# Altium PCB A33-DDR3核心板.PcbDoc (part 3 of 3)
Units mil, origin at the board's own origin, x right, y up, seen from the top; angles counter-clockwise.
Board outline 2370 x 2515 mil, 4 copper layers (TOP, GND02, PWR03, BOTTOM), stack 38.4 mil thick; 39 components, 64 nets, 546 pads, 403 vias.
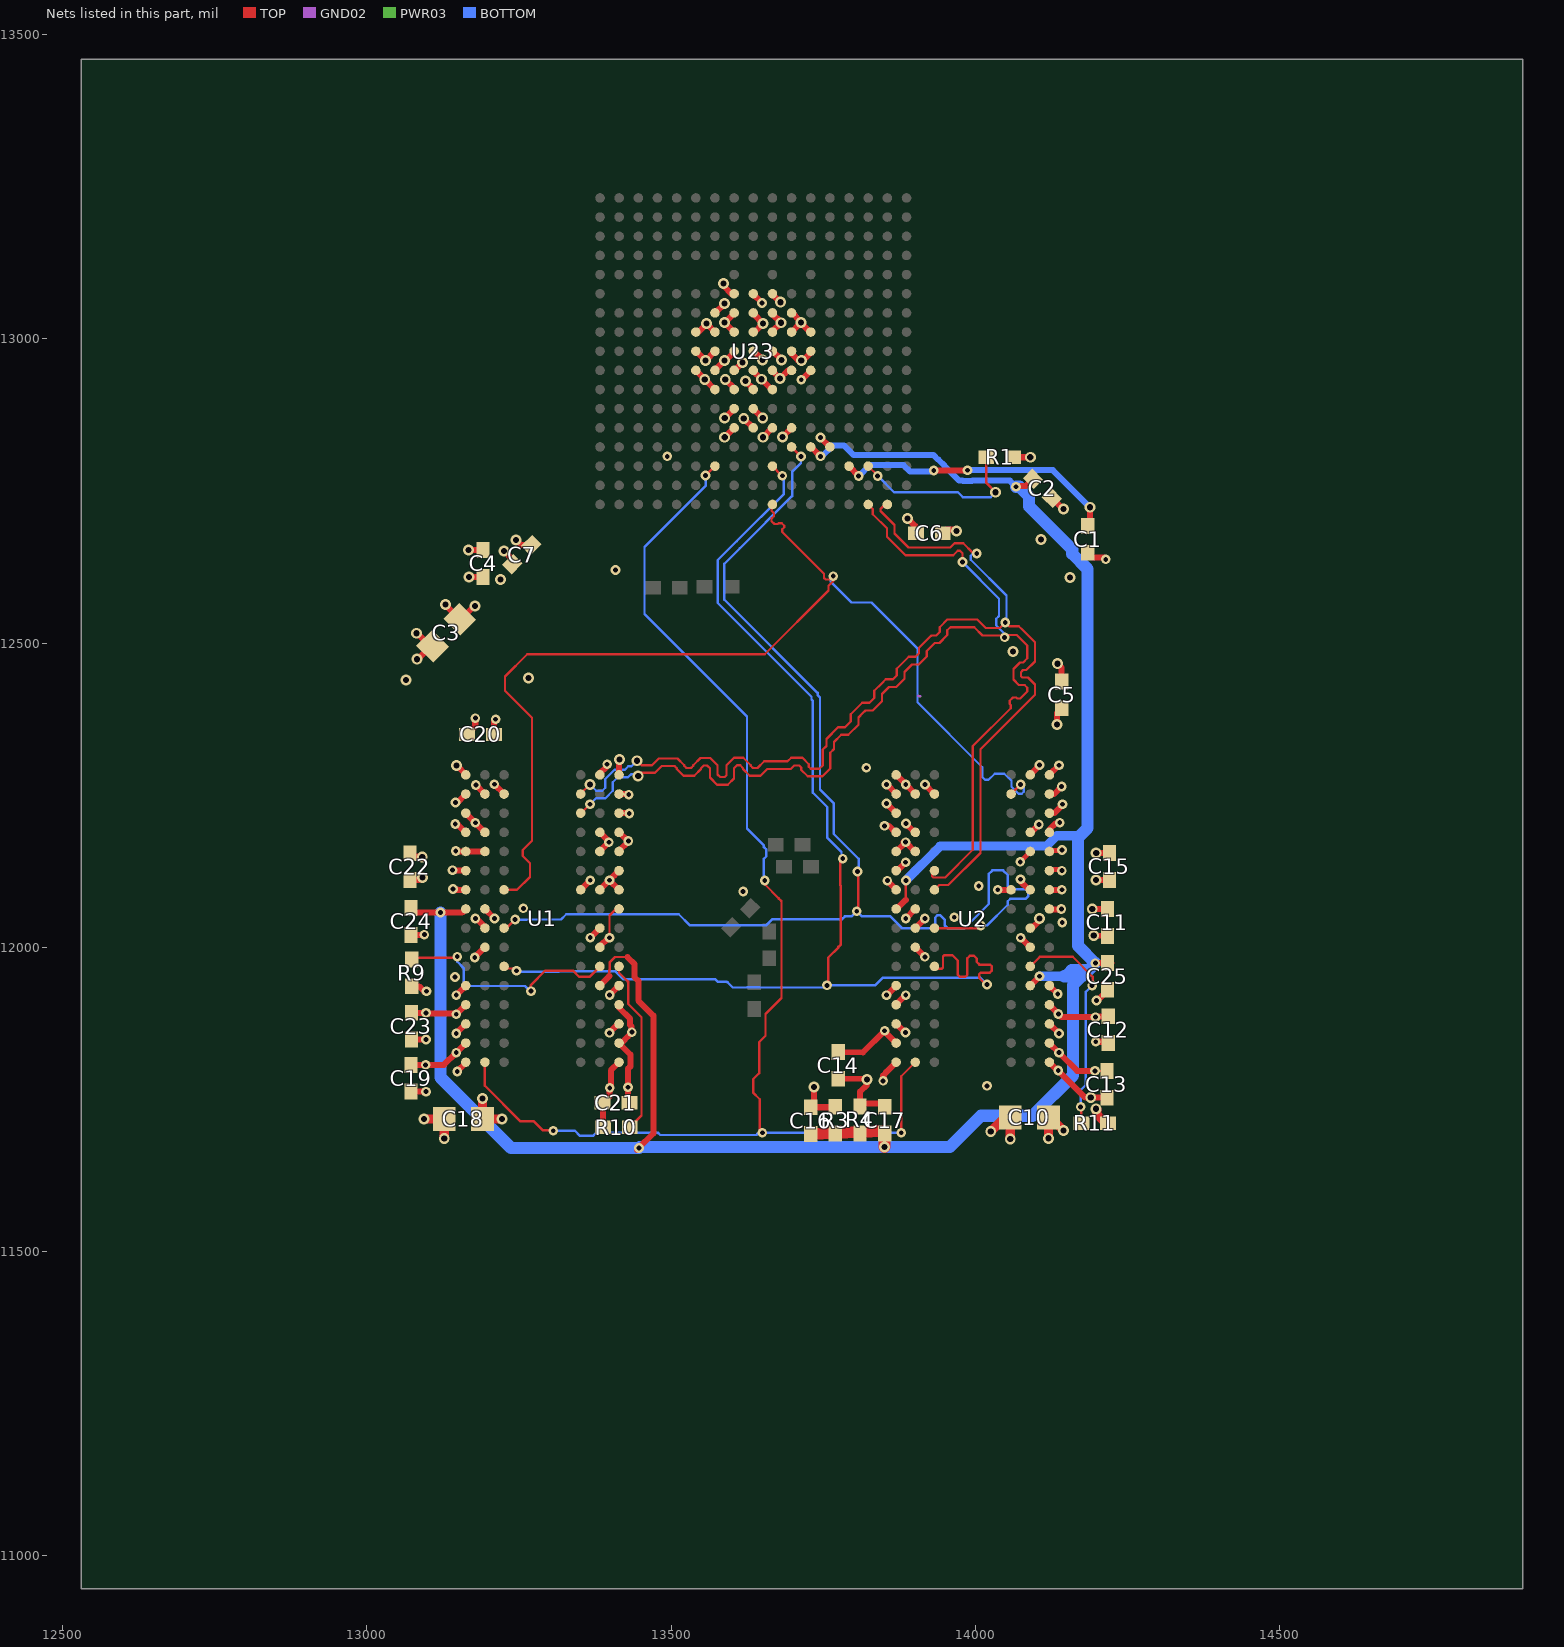
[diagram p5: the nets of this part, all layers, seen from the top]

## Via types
v1: diameter 16, hole 8, TOP to BOTTOM, 320 vias
v2: diameter 18, hole 10, TOP to BOTTOM, 83 vias

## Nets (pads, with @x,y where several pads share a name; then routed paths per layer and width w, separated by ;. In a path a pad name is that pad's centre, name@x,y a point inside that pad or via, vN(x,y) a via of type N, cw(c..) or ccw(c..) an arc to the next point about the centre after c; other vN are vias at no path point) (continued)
DQS0N: U1.G3 U2.B7 U23.K1 | length 1804.6
  TOP w3.7: U1.G3@13225.37,12094.33 13246.7,12094.33 13267.86,12115.48 13267.86,12138 13255.93,12149.93 13255.93,12159.62 13271.34,12175.04 13271.34,12377.18 13226.81,12421.71 13226.81,12444.98 13263.25,12481.43 13653.82,12481.43 13758.75,12586.36 13758.75,12594.3 13766.62,12602.17 v1(13766.62,12609.97) 13761.01,12604.37 13753.99,12604.37 13751.48,12606.88 13751.48,12613.98 13682.79,12682.67 13682.79,12686.92 13686.02,12690.15 13686.02,12692.97 13682,12696.99 13676.77,12696.99 13675.48,12695.71 13669.76,12695.71 13665.14,12700.32 13665.14,12704.63 13668.93,12708.41 13668.93,12713.9 13665.14,12717.68 13665.14,12720.92 13666.56,12722.33 U23.K1@13666.56,12727.82
  TOP w4: U2.B7@14058.91,12251.81 v1(14074.66,12267.55)
  BOTTOM w3.7: v1(13766.62,12609.97) 13762.01,12605.36 13762.01,12601.32 13796.73,12566.59 13829.3,12566.59 13905.01,12490.88 13905.01,12402.58 14011.71,12295.88 14011.71,12279.65 14016.16,12275.2 14021.95,12275.2 14032.01,12285.26 14047.6,12285.26 14059.46,12273.4 14059.46,12263.75 14071.04,12252.16 14076.5,12252.16 14079.89,12255.56 14079.89,12262.32 v1(14074.66,12267.55)
DQS1: U1.C7 U2.F3 U23.R1 | length 1918.8
  TOP w3.7: U1.C7@13351.35,12220.31 13351.83,12220.31 v1(13366.49,12234.98) ; v2(13445.89,12281.28) 13451.26,12286.66 13473.6,12286.66 13484.68,12297.74 13505.45,12297.74 13509.15,12294.04 13509.15,12293.05 13520.17,12282.03 13537.92,12282.03 13548.95,12293.05 13548.95,12294.04 13553.52,12298.61 13559.17,12298.61 13563.75,12294.04 13563.75,12285.95 13563.75,12278.89 13575.46,12267.18 13593.23,12267.18 13603.55,12277.5 13603.55,12294.04 13608.44,12298.93 13613.45,12298.93 13618.35,12294.04 13618.35,12293.05 13629.37,12282.03 13647.12,12282.03 13658.15,12293.05 13696.68,12293.05 13702.5,12298.86 13710.64,12298.86 13713.96,12295.54 13713.96,12291.37 13724.47,12280.86 13748.9,12280.86 13761.71,12293.67 13761.71,12319.62 13767.76,12325.67 13767.76,12337.2 13779.67,12349.11 13791.2,12349.11 13807.89,12365.81 13807.89,12377.71 13814.67,12384.48 13819.43,12389.24 13831.33,12389.24 13846.5,12404.41 13846.5,12416.32 13858.04,12427.85 13869.94,12427.85 13883.5,12441.41 13883.5,12452.46 13895.9,12464.85 13896.53,12464.85 13906.94,12464.85 13920.13,12478.04 13920.13,12486.95 13933.25,12500.07 13941.05,12500.07 13954.07,12513.09 13954.07,12520.89 13959.26,12526.08 13998.22,12526.08 14011.89,12512.41 14045.23,12512.41 v1(14048.31,12509.33) ; U23.R1@13824.04,12727.82 13831.65,12720.21 13831.65,12711.93 13854.82,12688.76 13854.82,12674.74 13885.19,12644.38 13963.97,12644.38 13971.2,12651.6 13975.07,12651.6 13978.89,12647.78 v1(13978.89,12633.06) ; U2.F3@13932.93,12125.83 13928.74,12121.64 13928.74,12117 13931.04,12114.7 13950.55,12114.7 13995.99,12160.14 13995.99,12330.56 14058.37,12392.94 14058.37,12398.18 14056.71,12399.84 14056.71,12405.07 14061.94,12410.31 14067.17,12410.31 14068.84,12408.64 14074.07,12408.64 14085.63,12420.2 14085.63,12426.63 14081.44,12430.82 14071.92,12430.82 14062.7,12440.04 14062.7,12457.28 14073.47,12468.05 14078.7,12468.05 14085.63,12474.98 14085.63,12496.02 14068.38,12513.26 14052.24,12513.26 v1(14048.31,12509.33) ; v1@14048.31,12508.28 v1(14048.31,12509.33)
  BOTTOM w3.7: v1(13366.49,12234.98) 13376.34,12244.83 13391.99,12244.83 13404.2,12257.03 13404.2,12271.17 13412.26,12279.24 13429.16,12279.24 13434.69,12284.77 13442.4,12284.77 v2(13445.89,12281.28) ; v1(13978.89,12633.06) 14039.06,12572.89 14039.06,12544.54 14034.55,12540.03 14034.55,12528.8 14048.31,12515.04 v1(14048.31,12509.33)
DQS1N: U1.B7 U2.G3 U23.T1 | length 1931.6
  TOP w3.7: U1.B7@13351.35,12251.81 13351.35,12252.48 13366.03,12267.16 13366.36,12267.16 v2(13366.65,12267.45) ; v2@13444.09,12306.48 13451.41,12299.16 13468.42,12299.16 13479.5,12310.24 13510.62,12310.24 13521.65,12299.22 13521.65,12298.23 13525.35,12294.53 13532.75,12294.53 13536.45,12298.23 13536.45,12299.22 13548.34,12311.11 13564.35,12311.11 13576.25,12299.21 13576.25,12284.07 13580.64,12279.68 13588.05,12279.68 13591.05,12282.67 13591.05,12299.22 13603.26,12311.43 13618.63,12311.43 13630.85,12299.22 13630.85,12298.23 13634.55,12294.53 13641.95,12294.53 13652.97,12305.55 13691.51,12305.55 13697.32,12311.36 13715.82,12311.36 13726.46,12300.72 13726.46,12296.55 13729.65,12293.36 13743.72,12293.36 13749.21,12298.84 13749.21,12324.8 13755.26,12330.85 13755.26,12336.08 13755.26,12342.38 13774.5,12361.61 13786.02,12361.61 13795.39,12370.98 13795.39,12382.89 13814.25,12401.74 13826.15,12401.74 13834,12409.59 13834,12421.49 13846.97,12434.46 13852.86,12440.35 13864.76,12440.35 13871,12446.59 13871,12457.63 13890.72,12477.35 13896.53,12477.35 13901.76,12477.35 13907.63,12483.22 13907.63,12492.13 13924.04,12508.54 13928.07,12512.57 13935.88,12512.57 13941.57,12518.26 13941.57,12526.07 13954.08,12538.58 14003.4,12538.58 14017.07,12524.91 14040.43,12524.91 v1(14049.4,12533.88) 14055.62,12527.65 14071.67,12527.65 14077.22,12522.1 14098.13,12501.19 14098.13,12469.8 14083.87,12455.55 14078.65,12455.55 14075.2,12452.1 14075.2,12445.22 14077.1,12443.32 14086.61,12443.32 14098.13,12431.81 14098.13,12415.02 14008.49,12325.38 14008.49,12154.96 13955.73,12102.2 13940.8,12102.2 U2.G3@13932.93,12094.33 ; U23.T1@13855.53,12727.82 13851.76,12727.82 13844.15,12720.21 13844.15,12717.11 13867.32,12693.94 13867.32,12679.92 13890.36,12656.88 13958.8,12656.88 13966.02,12664.1 13980.25,12664.1 13995.64,12648.71 14000.94,12648.71 v1(14002.55,12647.11)
  BOTTOM w3.7: v2(13366.65,12267.45) 13376.77,12257.33 13386.81,12257.33 13391.7,12262.21 13391.7,12276.35 13407.09,12291.74 13423.98,12291.74 13429.52,12297.27 13434.84,12297.27 v2(13444.04,12306.48) ; v1(14002.55,12647.11) 13996.25,12647.11 13992.74,12643.59 13992.74,12636.89 14051.56,12578.07 14051.56,12539.36 14049.4,12537.2 v1(14049.4,12533.88)
DRAS: U1.J3 U2.J3 U23.L4 | length 2126.7
  TOP w4: U1.J3@13225.37,12031.34 13229.53,12031.34 v1(13243.53,12045.34) ; U23.L4@13698.05,12822.31 v1(13713.52,12806.84) ; v1(13805.08,12059.16) 13805.08,12062.51 13807.84,12065.27 13807.84,12123.1 v1(13806.47,12124.47) ; U2.J3@13932.93,12031.34 14004.87,12031.35 v1(14009.18,12035.65)
  BOTTOM w4: v1(13243.53,12045.34) 13262.97,12045.34 13263.1,12045.47 13318.79,12045.47 13327.53,12054.21 13512.48,12054.21 13530.43,12036.26 13656.65,12036.26 13666.53,12046.14 13781.2,12046.14 13785.56,12050.5 13796.41,12050.5 v1(13805.08,12059.16) 13813.15,12051.09 13859.74,12051.09 13879.48,12031.35 13930.17,12031.35 13934.17,12035.35 13934.17,12048.67 13938.17,12052.67 13941.88,12052.67 13950.17,12044.38 13950.17,12035.35 13954.17,12031.35 13982.71,12031.35 14022.29,12070.93 14022.29,12120.42 14028.08,12126.22 14045.89,12126.22 14053.51,12118.59 14053.51,12099.44 14057.51,12095.44 14082.89,12095.44 14086.89,12091.44 14086.89,12083.44 14082.89,12079.44 14057.51,12079.44 14053.51,12075.44 14053.51,12069.76 14019.41,12035.65 v1(14009.18,12035.65) ; v1(13713.52,12806.84) 13713.52,12796.19 13700.23,12782.9 13700.23,12782.73 13699.06,12781.55 13699.06,12777.32 13698.83,12777.09 13698.83,12741.62 13697.36,12740.16 13697.36,12740.11 13612.92,12655.66 13612.87,12655.66 13587.63,12630.43 13587.63,12571.22 13740.79,12418.06 13740.79,12414.64 13744.79,12410.64 13744.79,12259.08 13767.01,12236.86 13767.01,12186.52 13808.44,12145.09 13808.44,12127.53 13807,12126.09 13807,12125 v1(13806.47,12124.47)
DRST: U1.T2 U2.T2 U23.G3 | length 2154.7
  TOP w4: U1.T2@13193.87,11810.86 13193.87,11772.13 13252.38,11713.62 13274.28,11713.62 13289.16,11698.74 13305.61,11698.74 v1(13306.24,11698.11) ; v1@13557.75,12775.34 v1(13556.6,12775.34) U23.G3@13572.07,12790.81 ; v1(13649.95,11694.8) 13645.61,11699.14 13645.61,11749.96 13634.76,11760.81 13634.76,11782.8 13644.84,11792.88 13644.84,11844.1 13655.19,11854.45 13655.19,11890.19 13681.49,11916.49 13681.49,12074.98 13680.77,12075.7 13680.77,12076.25 13676.77,12080.25 13676.77,12080.53 13654.77,12102.53 13654.77,12105.11 13653.82,12106.06 v1(13653.82,12109.68) ; v1(13878.28,11694.8) 13878.28,11787.72 U2.T2@13901.43,11810.87
  BOTTOM w4: v1(13306.24,11698.11) 13341.76,11698.11 13349.57,11690.3 13372.38,11690.3 13376.66,11694.58 13478.61,11694.58 13482.04,11691.15 13640.09,11691.15 13641.9,11692.96 13648.11,11692.96 v1(13649.95,11694.8) v1(13878.28,11694.8) ; v1(13556.6,12775.34) 13556.6,12758.45 13456.19,12658.04 13456.19,12547.64 13624.79,12379.03 13624.79,12194.88 13652.6,12167.08 13652.6,12164.55 13656.44,12160.71 13656.44,12149.11 13652.6,12145.27 13652.6,12110.91 v1(13653.82,12109.68)
DVREF: C2.2 C16.1 C17.2 C24.2 C25.2 R3.1 R4.2 U1.H1 U1.M8 U2.H1 U2.M8 U23.M4 | length 4210.7
  TOP w4: U1.M8@13382.85,11936.85 13382.85,11936.99 13398.28,11952.42 13398.28,11961.89 13398.87,11962.48 13398.87,11974.75 13407.94,11983.82 13428.18,11983.82 ; U23.M4@13729.55,12822.31 13744.59,12807.27 v1@13745.16,12807.27 ; R3.1@13769.95,11693.57 13810.14,11698.57 R4.2@13810.48,11693.91 13850.67,11698.91 C17.2@13851.01,11693.57 ; U2.H1@13869.94,12062.84 13884.77,12077.67 13886.03,12077.67 v1(13886.03,12109.67)
  TOP w10: C24.2@13072.35,12064.25 13079.44,12057.16 v1(13121.03,12057.16) 13121.46,12056.73 13156.27,12056.73 U1.H1@13162.38,12062.83 ; U1.M8@13382.85,11936.85 13398.28,11952.27 13398.28,11952.42 ; 13428.18,11983.82 13439.85,11972.15 13439.85,11950.88 13440.53,11950.2 13446.1,11944.62 13446.1,11912.17 13470.73,11887.53 13470.73,11693.69 v1(13447.03,11669.98) v1@13443.78,11666.74 ; U23.M4@13729.55,12822.31 13730.12,12822.31 13745.16,12807.27 v1(13745.49,12806.94) ; U2.H1@13869.94,12062.84 13871.2,12062.84 13886.03,12077.67 ; v1(14066.81,12756.87) 14068.34,12758.4 14083.56,12758.4 C2.2@14094.94,12769.78 ; U2.M8@14090.41,11936.85 v1(14105.72,11952.17) ; v1(14197.47,11973.71) 14223.9,11973.71 C25.2@14217.33,11973.85
  TOP w20: C16.1@13729.74,11692.88 13850.33,11697.88 C17.2@13851.01,11693.57 v2(13851.01,11671.57)
  BOTTOM w10: v1(13745.49,12806.94) 13748.05,12806.94 13765.67,12824.57 13784.54,12824.57 13800.23,12808.87 13931.51,12808.87 13938.63,12801.75 13939.15,12801.75 13949.69,12791.21 13949.69,12790.69 13973.46,12766.92 13979.19,12766.92 13979.85,12766.26 13994.68,12766.26 13995.34,12766.92 14056.76,12766.92 v1(14066.81,12756.87)
  BOTTOM w15: v1(13886.03,12109.67) 13942.47,12166.11 14116.84,12166.11 14133.89,12183.16 14172.04,12183.16 ; v1(14105.72,11952.17) 14146.42,11952.17 ; v1(14197.47,11973.71) v1@14197.47,11975.34
  BOTTOM w20: 13121.03,11882.57 13121.03,11785.61 13236.66,11669.98 v1(13447.03,11669.98) 13448.51,11671.46 v2@13851.12,11671.46 ; 13121.04,11882.58 13121.04,11901.56 v1(13121.03,12057.16) ; v2(13851.01,11671.57) v2@13851.12,11671.46 ; v1(14066.81,12756.87) 14072.63,12756.87 14088.59,12740.9 14088.59,12724.5 14159.5,12653.6 14159.5,12646.6 14184.55,12621.55 14184.55,12195.67 14172.04,12183.16 14168.88,12180 14168.88,12002.3 v1(14197.47,11973.71) 14186.01,11962.26 ; 14146.42,11952.17 14148.64,11952.17 14158.73,11962.26 14186.01,11962.26 ; v2@13851.12,11671.46 13957.99,11671.46 14009.29,11722.77 14094.21,11722.77 14160.64,11789.19 14160.64,11938.04 14184.36,11961.76 14185.52,11961.76 14186.01,11962.26
DWE: U1.L3 U2.L3 U23.K3 | length 2066.5
  TOP w4: v1(13245.76,11961.28) 13244.78,11962.25 13243.75,11962.25 13243.05,11962.95 13242.47,11962.95 13240.54,11964.89 13228.83,11964.89 U1.L3@13227.55,11966.17 ; U23.K3@13666.56,12790.81 13680.83,12776.54 13681.27,12776.54 v1(13682.81,12775) ; v1(13756.27,11937.19) 13758.22,11939.14 13758.22,11983.07 13774.87,11999.73 13774.87,12000.36 13779.2,12004.68 13779.2,12100.81 13777.93,12102.08 13777.93,12141.21 v1(13782.24,12145.52) ; U2.L3@13932.93,11968.35 13937.1,11964.18 13944.56,11964.18 13946.97,11966.58 13946.97,11984.56 13949.31,11986.89 13962.24,11986.89 13971.16,11977.97 13971.16,11954.94 13975.02,11951.08 13983.47,11951.08 13987.16,11954.77 13987.16,11981.82 13991.16,11985.82 13997.78,11985.82 14002.39,11981.21 14002.39,11975.86 14006.88,11971.38 14024.31,11971.38 14027.14,11968.55 14027.14,11961.45 14023.34,11957.66 14008.6,11957.66 14006.5,11955.55 14006.5,11949.52 14017.23,11938.8 v1@14019.22,11938.8 ; v1@14019.23,11938.79 v1(14019.3,11938.79) ; U1.L3@13227.55,11966.17 U1.L3@13225.37,11968.34 U1.L3@13227.55,11966.17
  BOTTOM w4: v1(13245.76,11961.28) 13246.74,11961.28 13248.59,11959.42 13258.02,11959.42 13258.2,11959.25 13314.58,11959.25 13316.07,11960.74 13407.73,11960.74 13421.52,11946.95 13573,11946.95 13576.5,11943.45 13591.2,11943.45 13592.6,11942.05 13593.02,11942.05 13601.37,11933.7 13624.56,11933.7 13624.98,11934.12 13644.87,11934.12 13645.29,11933.7 13752.78,11933.7 v1(13756.27,11937.19) 13835.24,11937.19 13848.11,11950.07 14008.02,11950.07 v1(14019.3,11938.79) ; v1(13682.81,12775) 13685.36,12772.45 13685.36,12745.08 13607.95,12667.66 13607.9,12667.66 13576.65,12636.42 13576.65,12625.11 13576.41,12624.88 13576.41,12566.16 13730.79,12411.78 13730.79,12407 13732.79,12405 13732.79,12254.11 13756.97,12229.93 13756.97,12179.59 13780.07,12156.48 13780.07,12147.69 v1(13782.24,12145.52)
DZQ: R1.2 U23.R3 | length 298.4
  TOP w3.7: U23.R3@13824.04,12790.81 13839.21,12775.64 13839.21,12775.07 v1(13839.58,12774.7)
  TOP w4: R1.2@14018.23,12805.45 14018.23,12763.23 v2(14033.58,12747.88)
  BOTTOM w4: v1(13839.58,12774.7) 13839.98,12774.7 13866.67,12748.01 13971.4,12748.01 13979.77,12739.64 14025.35,12739.64 v2(14033.58,12747.88)
GND: C1.1 C2.1 C3.1 C4.1 C5.1 C6.1 C7.1 C10.1 C11.1 C12.1 C13.2 C14.2 C15.2 C17.1 C18.1 C19.1 C20.1 C21.2 C22.2 C23.2 C24.1 C25.1 R1.1 R4.1 R9.1 R10.1 R11.1 U1.A9 U1.B1 U1.B3 U1.B9 U1.D1 U1.D8 U1.E1 U1.E2 U1.E8 U1.F9 U1.G1 U1.G8 U1.G9 U1.J2 U1.J8 U1.M1 U1.M9 U1.P1 U1.P9 U1.T1 U1.T9 U2.A9 U2.B1 U2.B3 U2.B9 U2.D1 U2.D8 U2.E1 U2.E2 U2.E8 U2.F9 U2.G1 U2.G8 U2.G9 U2.J2 U2.J8 U2.M1 U2.M9 U2.P1 U2.P9 U2.T1 U2.T9 U23.F8 U23.F9 U23.F10 U23.G7 U23.G8 U23.G9 U23.G10 U23.G11 U23.H7 U23.H8 U23.H9 U23.H10 U23.H11 U23.H12 U23.J7 U23.J8 U23.J9 U23.J10 U23.J11 U23.J12 U23.K7 U23.K8 U23.K9 U23.K10 U23.K11 U23.K12 U23.L8 U23.L9 U23.L10 U23.L11 U23.M8 U23.M9 U23.M10 U23.N4 | length 3159.8
  TOP w3.7: v1(13745.53,12837.94) 13745.53,12837.59 13760.81,12822.31 U23.N4@13761.04,12822.31
  TOP w4: v1(13146.63,11858.12) U1.P1@13162.38,11873.86 ; v1@13148.18,12094.33 U1.G1@13162.38,12094.33 ; v1(13178.13,12047.09) U1.J2@13193.87,12031.34 U1.J2@13193.87,12033.75 ; v1(13367.1,12015.6) U1.J8@13382.85,12031.34 ; U1.G8@13382.85,12094.33 v1(13398.59,12110.08) ; 13400.84,11797.36 U1.T9@13414.35,11810.86 ; U1.M9@13412.91,11935.42 U1.M9@13414.35,11936.85 ; U23.F9@13540.57,12979.79 U23.F9@13541.13,12979.79 ; U23.F10@13544.51,13011.29 13545.27,13011.29 v2@13558.31,13024.33 ; v2(13558.31,13025.1) v2@13558.31,13024.33 ; U23.G10@13572.07,13011.29 13569.54,13011.29 13558.31,13022.51 v2@13558.31,13024.33 ; v2(13588.09,13026.76) 13603.56,13042.23 U23.H11@13603.56,13042.78 ; U23.J8@13635.06,12947.19 U23.J8@13635.06,12948.3 ; U23.J9@13635.06,12979.79 U23.J9@13636.2,12979.79 ; U23.J11@13635.06,13042.78 13635.06,13040.9 U23.J11@13636.56,13039.4 ; U23.K12@13666.56,13073.5 U23.K12@13666.56,13074.28 ; v1(13848.63,11780.27) 13851.79,11783.43 13851.79,11792.72 13853.6,11794.53 ; 13853.6,11793.94 13869.94,11810.28 U2.T1@13869.94,11810.87 ; v1@13856.81,12107.46 U2.G1@13869.94,12094.33 ; U2.E1@13869.94,12157.33 U2.E1@13870.2,12157.33 ; U2.D8@14090.41,12188.82 U2.D8@14091.83,12188.82 ; U2.T9@14121.9,11810.87 14122.83,11810.87 v1(14136.53,11797.17) ; U2.P9@14121.9,11873.86 v1(14137.64,11858.12) ; U2.F9@14121.9,12125.83 U2.F9@14125.79,12125.83 ; R11.1@14214.88,11710.53 14214.98,11710.43 R11.1@14218.47,11710.43 ; U1.P9@13413.29,11873.86 U1.P9@13414.35,11873.86 U1.P9@13413.29,11873.86
  TOP w8: v1(14073.96,12140.3) 14090.41,12156.74 U2.E8@14090.41,12157.33 ; U2.F9@14121.9,12125.83 U2.F9@14125.78,12125.82 ; U2.F9@14125.79,12125.83 14127.37,12127.41 14140.79,12127.41 v1(14142.38,12125.82)
  TOP w10: C22.2@13070.7,12110.27 13086.33,12110.27 13090.73,12114.67 v2(13091.44,12114.67) ; C24.1@13072.35,12020.25 13093.89,12020.25 v1(13094.24,12020.59) ; C19.1@13072.42,11762.51 v1(13097.02,11762.51) ; C23.2@13073.14,11848.3 v1(13097.14,11848.3) ; R9.1@13073.82,11935.62 13085.57,11935.62 13093.7,11927.48 v1(13097.82,11927.48) ; v2(13128.76,12563.17) 13130.29,12561.64 13130.29,12561.5 C3.1@13152.48,12539.26 C3.1@13152.48,12539.26 13154.94,12539.26 13176.74,12561.05 v2(13177.7,12561.05) ; v1(13141.54,12095.52) 13146.99,12095.52 13148.17,12094.34 U1.G1@13162.38,12094.33 ; v1(13145.2,12202.35) 13146.63,12202.35 13147.76,12201.22 13149.37,12201.22 13161.77,12188.82 U1.D1@13162.38,12188.82 ; v1(13145.66,12237.71) 13148.28,12237.71 U1.B1@13162.38,12251.81 ; v1(13146.01,12158.15) 13146.78,12157.38 U1.E1@13162.43,12157.38 ; v1(13146.63,11858.12) U1.P1@13162.38,11873.86 ; v1(13146.63,11921.12) U1.M1@13162.38,11936.85 ; v1(13148.34,11795.42) 13149.55,11796.62 13149.55,11796.74 13162.38,11809.57 U1.T1@13162.38,11810.86 ; U1.E1@13162.38,12157.32 U1.E1@13162.43,12157.38 ; C20.1@13164.65,12349.73 13178,12363.08 13178,12376.37 v1(13178.12,12376.5) ; v2(13167.03,12652.78) C4.1@13190.73,12652.78 ; v1(13178.13,12047.09) 13180.53,12047.09 U1.J2@13193.87,12033.75 ; U1.E2@13193.87,12157.32 13184.73,12157.32 13184.67,12157.38 U1.E1@13162.43,12157.38 ; v1(13209.41,12267.91) 13209.41,12267.7 13225.3,12251.81 U1.B3@13225.37,12251.81 ; v2(13225.37,12651.51) 13239.07,12637.81 C7.1@13239.07,12629.85 ; v1(13367.1,12015.6) U1.J8@13382.85,12031.34 ; U1.G8@13382.85,12094.33 13406.51,12117.99 ; U1.E8@13382.85,12157.32 13382.85,12157.8 v1(13397.65,12172.6) ; U1.D8@13382.85,12188.82 13397.65,12174.02 v1(13397.65,12172.6) ; C21.2@13387.87,11744.1 13398.59,11754.83 13398.59,11755.45 ; R10.1@13388.09,11704.12 13388.09,11743.46 C21.2@13387.35,11744.2 13398.59,11755.45 ; v1@13397.09,12172.6 v1(13397.65,12172.6) ; v1(13398.59,11859.16) U1.P9@13413.29,11873.86 ; v1@13399.72,11923.36 13399.72,11922.33 v1(13398.88,11921.49) 13398.99,11921.49 U1.M9@13412.91,11935.42 ; U1.G9@13414.35,12094.33 v1(13398.59,12110.08) 13406.51,12118 ; U1.F9@13414.35,12125.82 13406.51,12118 ; U1.B9@13414.35,12251.81 13427.11,12251.81 13428.18,12250.74 v1(13430.36,12250.74) ; U1.A9@13414.35,12283.31 13414.35,12305.11 13415.36,12306.13 13415.36,12308.14 v2(13415.45,12308.24) ; U1.T9@13415.14,11811.67 U1.T9@13414.35,11810.86 13400.84,11797.37 13400.84,11770.46 v1(13399.09,11768.71) 13399.09,11763.92 13398.59,11763.42 13398.59,11755.45 ; U23.F8@13540.57,12948.3 13540.57,12948.18 v2(13555.29,12933.46) 13571.95,12916.8 U23.G7@13572.07,12916.8 ; U23.F10@13540.57,13011.29 13544.51,13011.29 v2(13558.31,13025.1) U23.G10@13572.07,13011.29 U23.G10@13572.07,13011.29 ; U23.F9@13541.13,12979.79 v2(13556.6,12964.32) U23.G9@13572.07,12979.79 ; U23.G8@13572.07,12948.3 13572.07,12948.71 v2(13587.94,12964.58) 13589.21,12964.58 13590.3,12965.68 13591.07,12965.68 13603.56,12978.17 U23.H9@13603.56,12979.79 ; U23.G11@13572.07,13042.78 13572.77,13042.78 v2(13588.06,13058.08) ; v2(13586.16,13091.01) 13586.16,13086.95 13598.84,13074.28 U23.H12@13603.56,13074.28 ; v2(13589.02,12933.27) 13603.56,12918.72 U23.H7@13603.56,12916.8 ; U23.H8@13603.56,12948.3 13604.54,12948.3 v2(13617.6,12961.36) ; U23.H10@13603.56,13011.29 v2(13588.09,13026.76) 13603.56,13042.23 U23.H11@13603.56,13042.78 ; v2(13622,12930.84) 13635.06,12917.78 U23.J7@13635.06,12916.8 ; U23.J8@13634.3,12948.73 13634.3,12947.95 13635.06,12947.19 v2(13648.61,12933.65) 13665.45,12916.8 U23.K7@13666.56,12916.8 ; U23.J10@13635.06,13011.29 13637.05,13011.29 v2(13650.86,13025.1) ; U23.J12@13635.06,13074.28 13635.06,13073.5 v1(13649.36,13059.2) ; U23.J9@13636.18,12980.59 13636.18,12979.81 v2(13650.48,12965.51) ; U23.K8@13664.67,12950.04 13664.67,12949.26 U23.K8@13666.56,12947.37 ; U23.K12@13665.42,13075.41 13665.42,13074.63 13666.56,13073.5 v2(13679.72,13060.33) ; U23.K8@13666.56,12948.3 U23.K8@13666.56,12947.37 ; U23.K9@13666.56,12979.79 U23.K9@13667.31,12979.79 ; U23.K10@13666.56,13011.29 13666.56,13012.3 v2(13680.84,13026.59) ; U23.K11@13666.56,13042.78 U23.K11@13666.56,13040.88 ; U23.K9@13667.3,12980.59 U23.K9@13667.3,12979.81 ; v2(13681.6,12965.51) U23.K9@13667.31,12979.79 ; U23.L8@13698.05,12948.3 13692.31,12948.3 v2(13678.97,12934.95) U23.K8@13666.56,12947.37 ; U23.L9@13698.05,12979.79 13698.05,12975.29 13708.67,12964.67 v2(13713.99,12964.67) 13717.12,12964.67 13729.55,12977.1 U23.M9@13729.55,12979.79 ; U23.L10@13698.05,13011.29 13698.05,13011.37 13711.58,13024.9 v2(13713.47,13026.8) ; U23.L11@13698.05,13042.78 13698.95,13042.78 13711.58,13030.15 13711.58,13028.69 v2(13713.47,13026.8) ; v1(13714.03,12932.89) 13715,12932.89 13729.55,12947.43 U23.M8@13729.55,12948.3 ; U23.M10@13729.55,13011.29 13728.98,13011.29 v2(13713.47,13026.8) ; v1(13745.53,12837.94) 13761.04,12822.42 U23.N4@13761.04,12822.31 ; C14.2@13775.06,11783.81 13821.4,11783.03 v2(13822.12,11782.32) 13822.12,11782.24 13822.2,11782.16 13822.2,11774.07 13810.48,11762.35 R4.1@13810.48,11737.91 13814.8,11742.23 13820.3,11742.91 13845.67,11742.91 C17.1@13851.01,11737.57 ; v1(13848.63,11780.27) 13848.63,11788.97 13853.6,11793.94 13853.6,11794.53 U2.T1@13869.94,11810.87 ; v1(13850.84,12199.47) 13858.16,12199.47 13868.81,12188.82 U2.D1@13869.94,12188.82 ; v1(13854.19,11921.12) U2.M1@13869.94,11936.85 ; v1(13854.2,12267.56) U2.B1@13869.94,12251.81 ; v1(13855.47,12109.38) 13856.81,12108.05 13856.81,12107.47 U2.G1@13869.94,12094.33 ; U2.P1@13869.94,11873.86 13882.37,11861.44 13883.25,11861.44 v1(13885.14,11859.55) ; U2.E1@13869.94,12157.33 13870.2,12157.33 v1(13885.53,12172.66) ; v1@13882.48,12173.07 13882.9,12172.66 v1(13885.53,12172.66) ; U2.J2@13901.43,12031.34 v1(13917.17,12047.09) ; U2.E2@13901.43,12157.33 13900.86,12157.33 v1(13885.53,12172.66) ; v1(13917.19,12267.56) U2.B3@13932.93,12251.81 ; C6.1@13946.63,12680.77 13952.54,12686.69 13966.45,12686.69 v2(13968.93,12684.2) ; R1.1@14062.23,12805.45 v2(14090.46,12805.45) ; v1(14074.29,12111.72) 14074.29,12108.39 14088.36,12094.33 U2.G8@14090.41,12094.33 ; U2.D8@14090.41,12188.82 14091.83,12188.83 v1(14104.59,12201.59) ; U2.J8@14091.29,12031.35 14090.41,12031.35 14093.15,12031.34 14105.68,12043.87 v2(14105.75,12046.93) v2(14105.75,12046.93) ; U2.T9@14121.9,11810.87 14135.6,11797.17 v1(14136.53,11797.17) 14181.04,11752.65 v2(14189.91,11752.59) C13.2@14216.52,11752.39 ; U2.P9@14121.9,11873.86 v1(14137.64,11858.12) ; U2.M9@14121.9,11936.85 v1(14135.72,11923.01) ; U2.G9@14121.9,12094.33 v1(14142.38,12094.33) ; U2.B9@14121.9,12251.81 14129.66,12251.81 v1(14142.05,12264.2) ; U2.A9@14121.9,12283.31 v1(14137.65,12299.05) ; C2.1@14126.05,12738.67 14126.49,12738.67 v2(14144.89,12720.27) ; v2(14134.15,12365.87) 14134.15,12384.99 14141.93,12392.77 C5.1@14141.93,12392.87 ; C1.1@14185.25,12648.55 14193.44,12640.36 14211.77,12640.36 v1(14214.54,12637.59) ; v2(14192.37,12062.59) C11.1@14217.37,12062.59 ; v1(14198.12,11844.52) 14221.67,11844.52 C12.1@14218.69,11842.32 ; v2(14198.62,12110.68) C15.2@14220.62,12110.68 ; v1(14199.22,11912.41) 14201.06,11912.41 14218.5,11929.85 C25.1@14217.33,11929.85 ; v2(13650.86,13025.1) 13650.86,13025.87 13636.56,13040.18 13636.56,13039.4 v2(13650.86,13025.1) ; U23.K11@13666.54,13040.9 13666.54,13041.68 13680.84,13027.37 v2(13680.84,13026.59) ; U23.K11@13666.56,13040.88 v2(13680.84,13026.59)
  TOP w15: v2(13189.81,11751.43) 13189.99,11751.25 C18.1@13189.99,11717.8 v2(13221.65,11717.8) ; v2(14120.53,11685.81) C10.1@14120.53,11720.11 14123.61,11720.11 v2(14145.38,11698.34) ; v2(14198.78,11734.32) 14200,11733.1 14200,11725.42 14214.88,11710.53 R11.1@14214.88,11710.43
  GND02 w4: 13906.33,12413.61 13907.72,12412.22 13909.99,12412.22
  PWR03 w3.7: v1(13714.03,12932.89) v1@13715.23,12932.89
  BOTTOM w4: v2@13583.52,13055.53 13585.52,13055.53 v2(13588.06,13058.08) ; 13707.49,13038.24 13711.58,13031.71 13711.58,13028.69 v2(13713.47,13026.8)
  BOTTOM w8: v2@13583.52,13055.53 13583.23,13054.64 v2@13587.29,13057.6
  BOTTOM w15: v2@13587.29,13057.6 13586.84,13058.25 v2@13588.09,13058.25
  other v1: 14019.41,11772.05 13144.85,11951.09 14143.1,12040.52 13965.53,12049.17 13257.02,12063.79 13618.36,12091.69 14005.83,12100.41 13821,12295.04 13408.57,12619.98 13493.53,12806.92
  other v2: 13064.01,12439.46 13265.23,12442.61 14062.2,12486.32 13219.62,12604.18 14155.97,12607.76 14108.17,12670.2
N17523254: R11.2 U2.L8 | length 372.3
  TOP w4: U2.L8@14090.41,11968.35 14106.23,11984.17 14160.23,11984.17 14192.93,11951.47 14192.93,11937.76 v1(14192.15,11936.98) ; v1(14173.28,11737.53) 14174.47,11736.33 R11.2@14174.47,11710.43
  BOTTOM w4: v1(14173.28,11737.53) 14173.55,11737.81 14173.55,11765.56 14181.88,11773.89 14181.88,11926.76 v1@14192.11,11936.98
N18071026: R9.2 U1.L8 | length 386.8
  TOP w4: R9.2@13073.82,11979.62 13078.61,11982.37 13146.28,11982.37 v1(13148.33,11984.4) ; v1(13269.54,11927.73) 13269.54,11937.77 13293.13,11961.36 13338.72,11961.36 13349,11951.08 13365.59,11951.08 U1.L8@13382.85,11968.34
  BOTTOM w4: v1@13144.53,11984.63 13148.1,11984.63 v1(13148.33,11984.4) 13148.53,11984.19 13148.53,11976.1 13158.85,11965.79 13158.85,11943.8 13166.48,11936.17 13259.66,11936.17 13267.18,11928.65 13267.4,11928.65 13268.32,11927.73 v1(13269.54,11927.73)
N18071159: R10.2 U1.L9 | length 287.5
  TOP w4: U1.L9@13414.35,11968.34 13414.35,11958.01 13427.53,11944.82 13427.53,11944.7 13429.22,11943.01 13429.22,11928.08 ; 13429.23,11928.06 13429.23,11906.95 13451.35,11884.84 13451.35,11723.38 R10.2@13432.09,11704.12
VCC-DRAM: C3.2 C4.2 C5.2 C6.2 C7.2 C10.2 C11.2 C12.2 C13.1 C14.1 C15.1 C16.2 C18.2 C19.2 C20.2 C21.1 C22.1 C23.1 R3.2 U1.A1 U1.A8 U1.B2 U1.C1 U1.C9 U1.D2 U1.D9 U1.E9 U1.F1 U1.G7 U1.H2 U1.H9 U1.K2 U1.K8 U1.N1 U1.N9 U1.R1 U1.R9 U2.A1 U2.A8 U2.B2 U2.C1 U2.C9 U2.D2 U2.D9 U2.E9 U2.F1 U2.G7 U2.H2 U2.H9 U2.K2 U2.K8 U2.N1 U2.N9 U2.R1 U2.R9 U23.H5 U23.H6 U23.J5 U23.J6 U23.K5 U23.L5 | length 2370.4
  TOP w4: v1(13140.53,12126.66) 13141.36,12125.82 U1.F1@13162.38,12125.82 ; v1(13146.63,11826.62) U1.R1@13162.38,11842.36 ; v1(13177.19,11983.05) 13193.87,11999.73 U1.K2@13193.87,11999.84 ; U1.H2@13193.87,12062.83 v1(13209.61,12047.09) ; v1(13367.09,12110.08) U1.G7@13351.35,12094.33 v1(13367.09,12110.08) ; U1.K8@13382.85,12001.22 13382.85,11999.85 v1(13398.59,12015.59) 13398.73,12015.73 13398.73,12052.32 13409.25,12062.83 U1.H9@13414.35,12062.83 ; U1.E9@13414.35,12157.32 13429.71,12172.69 v1(13429.71,12174.69) ; U1.R9@13420.12,11844.29 13418.19,11842.36 U1.R9@13414.35,11842.36 13414.73,11842.36 13425.49,11853.13 13428.96,11853.13 ; v1@13428.5,12174.67 13426.5,12174.67 13414.35,12186.82 U1.D9@13414.35,12188.82 13428.47,12174.69 v1@13429.23,12174.69 ; v1@13428.96,12174.67 13429.21,12174.42 v1@13429.45,12174.42 ; v1(13851,11862.59) 13854.19,11859.4 13854.19,11858.11 U2.R1@13869.94,11842.36 ; v1(13885.68,12047.09) U2.H2@13901.43,12062.84 ; U2.D2@13898.23,12191.03 13900.44,12188.82 U2.D2@13901.43,12188.82 ; U2.R9@14121.9,11842.36 v1(14137.64,11826.62) ; U2.E9@14121.9,12157.33 14123.63,12157.33 U2.E9@14125.45,12159.15 ; U2.D9@14121.9,12188.82 U2.D9@14121.9,12193.47 ; v1(14196.78,11796.65) 14197.04,11796.39 C13.1@14216.52,11796.39
  TOP w8: U2.E9@14125.45,12159.15 14138.73,12159.15 14138.88,12159.3 14139.81,12159.3 14140.09,12159.58 v1(14142.66,12159.58)
  TOP w10: C22.1@13070.7,12154.27 13075.76,12149.22 13089.63,12149.22 v2(13090.83,12148.01) ; C19.2@13072.42,11806.51 C19.2@13082.41,11806.51 ; C23.1@13073.14,11892.3 13074.83,11892.07 v1(13097.14,11892.07) 13098.14,11892.07 13099.06,11891.15 13145.1,11891.15 v1(13146.63,11889.62) U1.N1@13162.38,11905.35 ; v2(13081.72,12516.14) 13082.38,12516.14 13103.81,12494.71 C3.2@13104.99,12494.71 ; v2(13081.89,12473.42) 13083.71,12473.42 C3.2@13104.99,12494.71 ; C19.2@13082.44,11806.49 v1(13096.42,11806.49) 13126.49,11806.49 v1(13146.63,11826.62) U1.R1@13162.38,11842.36 ; C3.2@13107.93,12494.71 C3.2@13104.99,12494.71 ; v1(13140.53,12126.66) 13139.82,12125.94 13147.98,12125.94 13148.09,12125.83 U1.F1@13162.38,12125.82 ; v2(13147.11,12298.97) 13147.26,12298.97 13162.38,12283.85 U1.A1@13162.38,12283.31 ; U1.C1@13162.38,12220.31 v1(13178.12,12204.57) U1.D2@13193.87,12188.82 ; v2(13167.94,12608.78) C4.2@13190.73,12608.78 ; v1(13177.19,11983.05) 13177.19,11983.16 U1.K2@13193.87,11999.84 ; v1(13179.01,12266.67) U1.B2@13193.87,12251.81 ; U1.H2@13193.87,12062.83 v1(13209.61,12047.09) ; C20.2@13208.65,12349.73 13208.65,12371.9 v1(13211.47,12374.73) ; v2(13245.06,12669.75) 13253.84,12660.97 C7.2@13270.19,12660.97 ; U1.G7@13351.35,12094.33 v1(13367.09,12110.08) ; U1.K8@13382.85,12001.22 13397.22,12015.59 v1(13398.59,12015.59) ; U1.A8@13382.85,12283.31 13382.85,12285.67 13392.98,12295.8 13392.98,12298.66 13394.8,12300.48 v1(13394.8,12300.65) ; U1.N9@13414.35,11905.35 13414.35,11900.63 13432.53,11882.45 13432.53,11871.79 13434.57,11869.76 13434.57,11861.67 13435.42,11860.81 v1(13435.42,11860.3) ; U1.E9@13414.35,12157.32 13414.35,12158.51 13429.21,12173.38 13429.21,12174.42 v1@13429.21,12174.67 ; U1.D9@13414.35,12188.82 13428.5,12174.67 13428.96,12174.67 v1@13429.21,12174.67 ; U1.C9@13414.35,12220.31 13414.76,12220.73 13429.95,12220.73 v1(13431.1,12219.58) ; v1@13429.23,12174.69 v1(13429.71,12174.69) ; v1@13429.45,12174.42 v1@13429.21,12174.67 ; C21.1@13431.35,11744.2 13429.23,11746.32 C21.1@13429.23,11746.74 ; C21.1@13431.87,11744.1 C21.1@13429.23,11746.74 ; v1@13435.62,11859.78 13428.96,11853.13 13420.12,11844.29 13416.26,11844.29 U1.R9@13414.35,11842.36 13433.14,11823.57 13433.14,11804.22 13429.23,11800.31 v1(13429.23,11769.69) C21.1@13429.23,11746.74 ; v2(13588.1,12838.35) U23.H5@13603.56,12853.81 ; v2(13588.1,12869.84) U23.H6@13603.56,12885.3 ; v2(13619.41,12869.09) 13634.71,12853.81 U23.J5@13635.06,12853.81 ; U23.J6@13635.06,12885.3 13650.45,12869.91 v2(13650.6,12869.91) ; v2(13651.1,12838.35) U23.K5@13666.56,12853.81 ; v2(13683.13,12838.7) 13698.05,12853.62 U23.L5@13698.05,12853.81 ; v2(13734.69,11770.31) 13734.69,11746.83 C16.2@13729.74,11736.88 13769.26,11736.88 R3.2@13769.95,11737.57 ; C14.1@13775.06,11827.81 13815.44,11827.03 v1(13851,11862.59) 13851,11861.3 U2.R1@13869.94,11842.36 ; v1(13854.2,12236.06) U2.C1@13869.94,12220.32 ; U2.N1@13869.94,11905.36 13869.94,11906.31 13884.74,11921.11 v1(13885.68,11921.11) ; U2.F1@13869.94,12125.83 13871.77,12125.83 v1(13885.61,12139.62) ; U2.A1@13869.94,12283.31 v1(13885.69,12267.56) U2.B2@13901.43,12251.81 ; v1(13885.68,12047.09) U2.H2@13901.43,12062.84 ; v1(13886.05,12203.21) U2.D2@13898.23,12191.03 ; v2(13888.8,12704.84) 13901.45,12692.19 C6.2@13902.63,12680.77 ; U2.K2@13901.43,11999.84 v1(13917.17,11984.1) ; v1(14037.03,12094.34) U2.G7@14058.91,12094.33 ; v1(14074.66,12015.59) U2.K8@14090.41,11999.84 ; U2.A8@14090.41,12283.31 14100.96,12293.86 14100.96,12294.78 v1(14105.71,12299.53) v1@14105.51,12299.73 ; U2.R9@14121.9,11842.36 v1(14137.64,11826.62) 14167.61,11796.65 v1(14196.78,11796.65) ; U2.N9@14121.9,11905.36 14136.57,11890.68 v1(14136.57,11889.96) 14141.58,11884.95 v1(14197.61,11884.95) 14198.98,11886.32 C12.2@14218.69,11886.32 C12.2@14216.8,11884.43 ; U2.H9@14121.9,12062.84 14122.92,12061.82 14140.51,12061.82 v1(14141.52,12062.83) ; U2.D9@14121.9,12193.47 14131.97,12203.54 14137.85,12203.54 v1(14139.02,12204.71) ; U2.C9@14121.9,12220.32 14130.06,12220.32 14143.26,12233.52 v1(14143.26,12234.93) ; v2(14135.49,12466.01) 14141.93,12459.57 C5.2@14141.93,12436.87 ; v2(14194.77,12018.9) C11.2@14217.37,12018.59 ; v2(14198.88,12154.68) C15.1@14220.62,12154.68
  TOP w15: v2(13093.42,11717.8) C18.2@13126.99,11717.8 v2(13126.99,11685.74) ; v2(14025.51,11696.91) 14048.71,11720.11 C10.2@14057.53,11720.11 v2(14057.53,11684.6)
  BOTTOM w4: v1(13886.05,12203.21) 13886.05,12203.01 v1@13887.66,12201.4
  BOTTOM w10: v1(14142.66,12159.58) 14142.94,12159.3 14144.11,12159.3 v1@14144.75,12158.66
VDD-DLL: C1.2 U23.P3 | length 496
  TOP w3.7: U23.P3@13792.54,12790.81 13808.32,12775.04 v1(13808.32,12774.52)
  TOP w10: U23.P3@13792.54,12790.81 13792.54,12790.3 v1(13808.32,12774.52) ; v1(13931.7,12783.76) 13985.74,12783.76 13986.14,12784.16 v1(13987.27,12784.16) ; C1.2@14185.25,12692.55 14188.55,12695.86 v2(14188.55,12723.26)
  BOTTOM w10: v1(13808.32,12774.52) 13826.49,12792.69 13881.78,12792.69 13892.4,12782.08 13929.76,12782.08 13931.44,12783.76 v1(13931.7,12783.76) ; v1(13987.27,12784.16) 14127.65,12784.16 v2(14188.55,12723.26)
pads on no net: U2.J1 U2.J9 U2.L1 U2.L9 U23.A2 U23.A3 U23.A4 U23.A5 U23.A6 U23.A7 U23.A8 U23.A9 U23.A10 U23.A11 U23.A12 U23.A13 U23.A14 U23.A15 U23.A16 U23.A17 U23.B2 U23.B3 U23.B4 U23.B5 U23.B6 U23.B7 U23.B8 U23.B9 U23.B10 U23.B11 U23.B13 U23.B14 U23.B15 U23.B16 U23.B17 U23.C3 U23.C4 U23.C5 U23.C6 U23.C7 U23.C8 U23.C9 U23.C10 U23.C11 U23.C12 U23.C13 U23.C14 U23.C15 U23.C16 U23.C17 U23.D3 U23.D4 U23.D5 U23.D6 U23.D7 U23.D8 U23.D9 U23.D10 U23.D11 U23.D12 U23.D13 U23.D14 U23.D15 U23.D16 U23.D17 U23.E5 U23.E6 U23.E7 U23.E8 U23.E9 U23.E10 U23.E11 U23.E12 U23.E14 U23.E15 U23.E16 U23.E17 U23.F5 U23.F6 U23.F7 U23.F11 U23.F12 U23.F14 U23.F15 U23.F16 U23.F17 U23.G5 U23.G6 U23.G12 U23.G14 U23.G15 U23.G16 U23.G17 U23.H13 U23.H14 U23.H15 U23.H16 U23.H17 U23.J14 U23.J15 U23.J16 U23.J17 U23.K6 U23.K13 U23.K14 U23.K15 U23.K16 U23.K17 U23.L6 U23.L12 U23.L14 U23.L15 U23.L16 U23.L17 U23.M5 U23.M6 U23.M7 U23.M11 U23.M12 U23.M13 U23.M14 U23.M15 U23.M16 U23.M17 U23.N6 U23.N8 U23.N9 U23.N10 U23.N11 U23.N12 U23.N14 U23.N15 U23.N16 U23.N17 U23.P4 U23.P5 U23.P6 U23.P7 U23.P8 U23.P9 U23.P10 U23.P11 U23.P12 U23.P13 U23.P14 U23.P15 U23.P16 U23.P17 U23.R4 U23.R5 U23.R6 U23.R7 U23.R8 U23.R9 U23.R10 U23.R11 U23.R12 U23.R13 U23.R14 U23.R15 U23.R16 U23.R17 U23.T4 U23.T5 U23.T6 U23.T7 U23.T8 U23.T9 U23.T10 U23.T11 U23.T12 U23.T13 U23.T14 U23.T15 U23.T16 U23.T17 U23.U4 U23.U5 U23.U6 U23.U7 U23.U8 U23.U9 U23.U10 U23.U11 U23.U12 U23.U13 U23.U14 U23.U15 U23.U16 U23.U17
copper on no net: | length 10182.9
  TOP w3.7: 13792.54,12822.31 13793.17,12822.31 v1(13808.72,12837.93) v1(13808.72,12837.93) ; 13792.54,12853.81 13792.92,12853.81 13808.59,12869.48 v1(13808.78,12869.48) ; 13792.54,12885.3 13792.54,12885.5 13807.79,12900.75 v1(13808.02,12900.75) ; 13792.54,12916.8 13792.85,12916.8 v1(13808.23,12932.17) ; 13824.04,12822.31 13825.59,12822.31 13840.03,12836.74 v1(13840.03,12838.08) ; 13824.04,12853.81 13825.05,12853.81 13840.28,12869.03 v1(13840.28,12869.48) ; 13824.04,12885.3 13824.57,12885.3 13839.28,12900.02 13839.28,12900.51 v1(13839.52,12900.75) ; 13824.04,12916.8 13824.04,12917.36 13837.61,12930.93 13838.01,12930.93 v1(13839.42,12932.34) ; 13887.03,12916.8 13890.64,12920.41
  TOP w4: 13509.07,12853.81 13509.07,12854.37 ; 13855.53,12822.31 13871.97,12805.87 13910.26,12805.87 13911.26,12806.88 13909.57,12806.88 13908.73,12806.04
  TOP w5: 12530,10945 12530,13460 14900,13460 14900,10945 12530,10945
  TOP w10: 13509.08,12853.81 13509.08,12854.36 ; v1(13714.25,12838.18) 13714.69,12838.61 13714.69,12838.95 13729.55,12853.81 ; 13729.55,12916.8 13744.07,12931.32 ; 13761.04,12885.3 13762.2,12885.3 13776.94,12870.56 v1(13776.94,12869.13)
  BOTTOM w4: v1@13779.15,12871.34 v1@13779.65,12871.34
  BOTTOM w10: v1(13714.25,12838.18) 13714.69,12838.61 13719.67,12838.61 13746.05,12864.99 13746.05,12870.02 v1(13776.66,12900.63) ; v1(13776.94,12869.13) v1@13779.15,12871.34

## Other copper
GND02:
  drawing of 285 lines, arcs and shapes, not listed
PWR03:
  drawing of 303 lines, arcs and shapes, not listed

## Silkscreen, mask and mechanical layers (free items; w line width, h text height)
Top Overlay:
  text "PCB联盟网（www.pcbbar.com），EDA技术学习好帮手！QQ群：610359600" at 12485,10845 h78.74
Mechanical 1:
  lines w1: 13369.59,12759.5 13984.2,12759.5 13984.2,13242.37 13369.59,13242.37 13369.59,12759.5
DIMENSION:
  lines w1: 8704.69,9764.15 8753.9,9764.15 ; 8704.69,9764.15 8729.29,9606.67 ; 8704.69,9764.15 8753.9,9764.15 ; 8704.69,9764.15 8729.29,9606.67 ; 8704.69,16490.85 8753.9,16490.85 ; 8704.69,16490.85 8729.29,16648.33 ; 8704.69,16490.85 8753.9,16490.85 ; 8704.69,16490.85 8729.29,16648.33 ; 8729.29,9606.67 8729.29,12925.14 ; 8729.29,9606.67 8753.9,9764.15 ; 8729.29,9606.67 8729.29,12925.14 ; 8729.29,9606.67 8753.9,9764.15 ; 8729.29,12925.14 8729.29,16648.33 ; 8729.29,12925.14 8729.29,16648.33 ; 8729.29,16648.33 8753.9,16490.85 ; 8729.29,16648.33 8753.9,16490.85 ; 9997.97,17692.16 13321.17,17692.16 ; 9997.97,17692.16 10155.45,17667.55 ; 9997.97,17692.16 10155.45,17716.77 ; 9997.97,17692.16 13321.17,17692.16 ; 9997.97,17692.16 10155.45,17667.55 ; 9997.97,17692.16 10155.45,17716.77 ; 10155.45,17667.55 10155.45,17716.77 ; 10155.45,17667.55 10155.45,17716.77 ; 12791.12,11816.67 12840.33,11816.67 ; 12791.12,11816.67 12815.73,11659.19 ; 12791.12,11816.67 12840.33,11816.67 ; 12791.12,11816.67 12815.73,11659.19 ; 12791.12,12546.35 12840.33,12546.35 ; 12791.12,12546.35 12815.73,12703.83 ; 12791.12,12546.35 12840.33,12546.35 ; 12791.12,12546.35 12815.73,12703.83 ; 12815.73,11659.19 12815.73,12127.69 ; 12815.73,11659.19 12840.33,11816.67 ; 12815.73,11659.19 12815.73,12127.69 ; 12815.73,11659.19 12840.33,11816.67 ; 12815.73,12127.69 12815.73,12703.83 ; 12815.73,12127.69 12815.73,12703.83 ; 12815.73,12703.83 12840.33,12546.35 ; 12815.73,12703.83 12840.33,12546.35 ; 13056.09,11424.57 13649.44,11424.57 ; 13056.09,11424.57 13213.57,11399.96 ; 13056.09,11424.57 13213.57,11449.17 ; 13056.09,11424.57 13649.44,11424.57 ; 13056.09,11424.57 13213.57,11399.96 ; 13056.09,11424.57 13213.57,11449.17 ; 13213.57,11399.96 13213.57,11449.17 ; 13213.57,11399.96 13213.57,11449.17 ; 13321.17,17692.16 16431.33,17692.16 ; 13321.17,17692.16 16431.33,17692.16 ; 13649.44,11424.57 14239.21,11424.57 ; 13649.44,11424.57 14239.21,11424.57 ; 14081.73,11399.96 14081.73,11449.17 ; 14081.73,11399.96 14239.21,11424.57 ; 14081.73,11399.96 14081.73,11449.17 ; 14081.73,11399.96 14239.21,11424.57 ; 14081.73,11449.17 14239.21,11424.57 ; 14081.73,11449.17 14239.21,11424.57 ; 16273.85,17667.55 16273.85,17716.77 ; 16273.85,17667.55 16431.33,17692.16 ; 16273.85,17667.55 16273.85,17716.77 ; 16273.85,17667.55 16431.33,17692.16 ; 16273.85,17716.77 16431.33,17692.16 ; 16273.85,17716.77 16431.33,17692.16 ; 8630.87,9606.67 10656.98,9606.67 8630.87,9606.67 ; 8630.87,16648.33 10275.89,16648.33 8630.87,16648.33 ; 9997.97,16555.04 9997.97,17790.59 9997.97,16555.04 ; 12717.3,11659.19 13468.51,11659.19 12717.3,11659.19 ; 12717.3,12703.83 13414.69,12703.83 12717.3,12703.83 ; 13056.09,11326.14 13056.09,11647.57 13056.09,11326.14 ; 14239.21,11326.14 14239.21,11649 14239.21,11326.14 ; 16431.33,16247.33 16431.33,17790.59 16431.33,16247.33
  text "163.4" at 13026.67,17754.66 h125
  text "163.4" at 13026.67,17754.66 h125
  text "178.9" at 8666.79,12630.64 h125 r90
  text "178.9" at 8666.79,12630.64 h125 r90
  text "26.4" at 12259.35,11912.49 h125 r90
  text "26.4" at 12259.35,11912.49 h125 r90
  text "26.5" at 12753.23,11895.19 h125 r90
  text "26.5" at 12753.23,11895.19 h125 r90
  text "30.1" at 13416.94,11487.07 h125
  text "30.1" at 13416.94,11487.07 h125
